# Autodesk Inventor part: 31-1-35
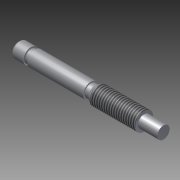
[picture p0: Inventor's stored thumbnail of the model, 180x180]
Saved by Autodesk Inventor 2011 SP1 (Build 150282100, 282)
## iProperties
Created: 2014-02
Part Number: 31-1-35
Document SubType Name: Modeling
Designer: Administrator
Density: 1 g/cm^3
Author: Administrator
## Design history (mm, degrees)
sketch "草图1"
  geometry: L1 (0, 8)-(11, 8); L2 (11, 8)-(11, 6.5); L3 (11, 6.5)-(15, 6.5); L4 (15, 6.5)-(15, 8); L5 (15, 8)-(73, 8); L6 (73, 8)-(73, 6.5); L7 (73, 6.5)-(77, 6.5); L8 (77, 6.5)-(81.096, 9.368); L9 (81.096, 9.368)-(128.096, 9.368); L10 (128.096, 9.368)-(128.096, 6.368); L11 (128.096, 6.368)-(148.096, 6.368); L12 (148.096, 6.368)-(148.096, 0); L13 (148.096, 0)-(0, 0); L14 (0, 0)-(-4, 0); A1 r 9.067 centre (5.055, 0.473) between (0, 8) and (-4, 0)
  constraints: 28 end point, 5 parallel, 3 perpendicular, 2 collinear, 2 point on circle, 1 centre point
  dimensions: "d0" = 8 distance of L13.end L1.start; "d1" = 11 distance of L1.start L1.end; "d2" = 1.5 distance of L1.end L2.end; "d3" = 4 distance of L2.end L3.end; "d4" = 1.5 distance of L3.end L4.end; "d5" = 58 distance of L4.end L5.end; "d6" = 1.5 distance of L5.end L6.end; "d7" = 4 distance of L6.end L7.end; "d8" = 5 distance of L7.end L8.end; "d9" = 145 deg angle of L8 L7; "d10" = 47 distance of L8.end L9.end; "d11" = 3 distance of L9.end L10.end; "d12" = 20 distance of L10.end L11.end
revolve "旋转1" sketch "草图1" stored, may be unused: angle "d14" = 90 deg
fillet "圆角1" dims "d15" = 1
feature "螺纹1" dims "d16" = 10, "d17" = 0
node "实体1"
